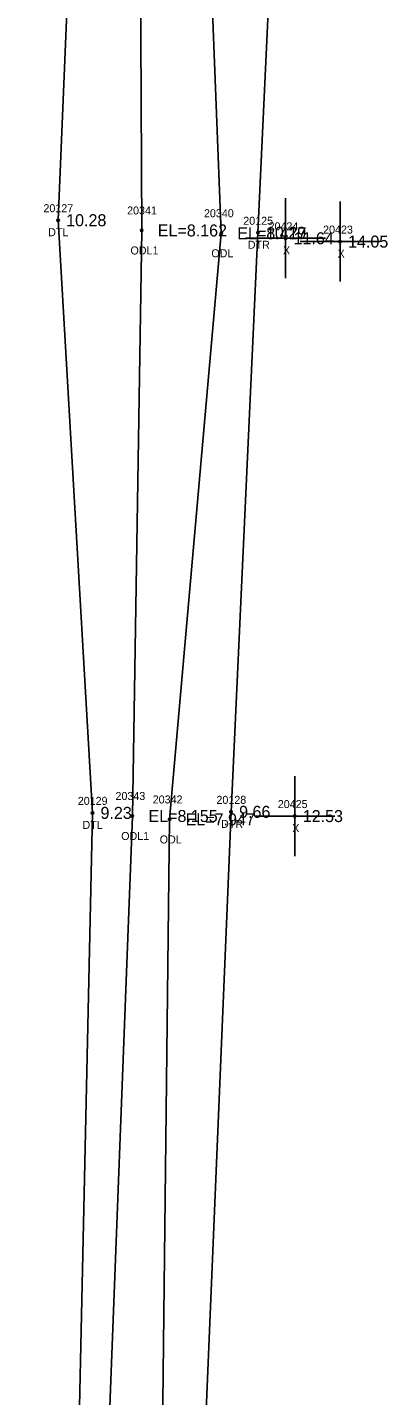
# Model space of a CAD drawing. Extents: x 2072302 to 2072980, y 127650 to 129736.
# Drawn here: x 2072397.2 to 2072442.2, y 129223 to 129394 of the extents above; entities that cross this region are included whole.
import ezdxf

# ---------------------------------------------------------------- set-up
doc = ezdxf.new("R2010")
doc.units = 0
for name, color, linetype in [('RD_EX_H2O', 7, 'Continuous'), ('RD_EX_H2O_txCode', 7, 'Continuous'), ('RD_EX_Misc', 7, 'Continuous'), ('RD_EX_Misc_txCode', 7, 'Continuous'), ('RD_EX_TX_H2O_ELEV', 7, 'Continuous'), ('RD_EX_TX_Misc_ELEV', 7, 'Continuous'), ('RD_SMD_Locator', 7, 'Continuous')]:
    doc.layers.add(name, color=color, linetype=linetype)

msp = doc.modelspace()

# ---------------------------------------------------------------- linework, layer by layer
at = {"layer": 'RD_EX_H2O'}
for points in [[(2072417.26, 129474.92), (2072421.43, 129368.24), (2072414.98, 129295), (2072413.35, 129153), (2072411.79, 129056.82)], [(2072430.99, 129475.23), (2072426.01, 129368.3), (2072422.66, 129295.95), (2072416.7, 129153.3), (2072414.39, 129056.34)], [(2072405.39, 129473.9), (2072401.06, 129369.87), (2072405.35, 129295.82), (2072402.29, 129156.96), (2072397.22, 129166.67)], [(2072410.97, 129474.07), (2072411.5, 129368.59), (2072410.34, 129295.43), (2072404.84, 129152.23), (2072403.87, 129055.61)]]:
    msp.add_lwpolyline(points, dxfattribs=at)
at = {"layer": 'RD_EX_Misc'}
for p, q in [((2072429.46, 129362.61), (2072429.46, 129372.61)), ((2072436.27, 129362.2), (2072436.27, 129372.2)), ((2072424.46, 129367.61), (2072434.46, 129367.61)), ((2072431.27, 129367.2), (2072441.27, 129367.2)), ((2072430.61, 129290.42), (2072430.61, 129300.42)), ((2072425.61, 129295.42), (2072435.61, 129295.42))]:
    msp.add_line(p, q, dxfattribs=at)
at = {"layer": 'RD_SMD_Locator'}
for centre in [(2072401.06, 129369.87), (2072411.5, 129368.59), (2072426.01, 129368.3), (2072421.43, 129368.24), (2072429.46, 129367.61), (2072436.27, 129367.2), (2072405.35, 129295.82), (2072410.34, 129295.43), (2072414.98, 129295), (2072422.66, 129295.95), (2072430.61, 129295.42)]:
    msp.add_circle(centre, 0.15, dxfattribs=at)

# ---------------------------------------------------------------- texts
at = {"layer": 'RD_EX_H2O_txCode'}
for s, p in [('20127', (2072399.22, 129370.87)), ('20341', (2072409.67, 129370.59)), ('20340', (2072419.27, 129370.24)), ('20125', (2072424.18, 129369.3)), ('DTL', (2072399.81, 129367.87)), ('DTR', (2072424.74, 129366.3)), ('ODL1', (2072410.09, 129365.59)), ('ODL', (2072420.19, 129365.24)), ('20343', (2072408.22, 129297.43)), ('20129', (2072403.51, 129296.82)), ('20342', (2072412.87, 129297)), ('20128', (2072420.83, 129296.95)), ('DTR', (2072421.4, 129293.95)), ('DTL', (2072404.1, 129293.82)), ('ODL1', (2072408.93, 129292.43)), ('ODL', (2072413.74, 129292))]:
    msp.add_text(s, height=1, dxfattribs=at).set_placement(p)
at = {"layer": 'RD_EX_Misc_txCode'}
for s, p in [('20424', (2072427.34, 129368.61)), ('20423', (2072434.15, 129368.2)), ('X', (2072429.14, 129365.61)), ('X', (2072435.96, 129365.2)), ('20425', (2072428.49, 129296.42)), ('X', (2072430.29, 129293.42))]:
    msp.add_text(s, height=1, dxfattribs=at).set_placement(p)
at = {"layer": 'RD_EX_TX_H2O_ELEV'}
for s, p in [('10.28', (2072402.06, 129369.12)), ('EL=8.162', (2072413.5, 129367.84)), ('EL=8.417', (2072423.43, 129367.49)), ('10.29', (2072427.01, 129367.55)), ('9.66', (2072423.66, 129295.2)), ('9.23', (2072406.35, 129295.07)), ('EL=8.155', (2072412.34, 129294.68)), ('EL=7.947', (2072416.98, 129294.25))]:
    msp.add_text(s, height=1.5, dxfattribs=at).set_placement(p)
at = {"layer": 'RD_EX_TX_Misc_ELEV'}
for s, p in [('11.64', (2072430.46, 129366.86)), ('14.05', (2072437.27, 129366.45)), ('12.53', (2072431.61, 129294.67))]:
    msp.add_text(s, height=1.5, dxfattribs=at).set_placement(p)

doc.saveas('drawing.dxf')
